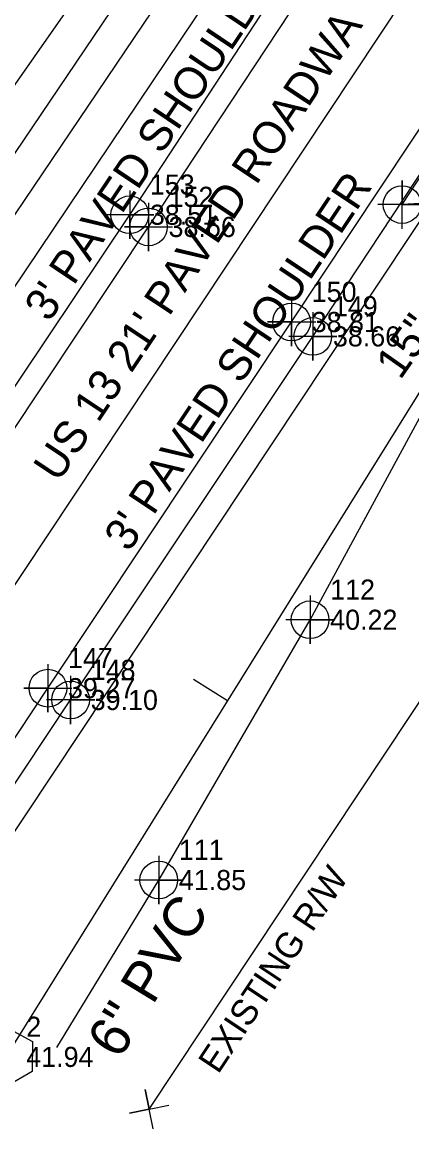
# Model space of a CAD drawing. Extents: x 2603627 to 2605187, y 896619 to 899063.
# Drawn here: x 2604072.2 to 2604120.7, y 897381.5 to 897519.1 of the extents above; entities that cross this region are included whole.
import ezdxf

# ---------------------------------------------------------------- set-up
doc = ezdxf.new("R2010")
doc.units = 0
for name, color, linetype in [('CTL GPS Vertical CELL', 7, 'Continuous'), ('CTL GPS Vertical Cogo Elevation', 7, 'Continuous'), ('CTL GPS Vertical Cogo Number', 7, 'Continuous'), ('Exist Horizontal Alignment', 7, 'Continuous'), ('Exist Horizontal Baseline Alignment', 7, 'Continuous'), ('Exist Horizontal Baseline Alignment Tick small', 7, 'Continuous'), ('Exist Property Corner CELL', 7, 'Continuous'), ('Exist Right of Way Line', 7, 'Continuous'), ('Exist Right of Way Line Text', 7, 'Continuous'), ('Exist Roads EOP', 7, 'Continuous'), ('Exist Roads EOP Cogo Elevation', 7, 'Continuous'), ('Exist Roads EOP Cogo Number', 7, 'Continuous'), ('Exist Roads EOP Cogo Point CELL', 7, 'Continuous'), ('Exist Roads EOP Text', 7, 'Continuous'), ('Exist Roads EOT', 7, 'Continuous'), ('Exist Roads EOT Cogo Elevation', 7, 'Continuous'), ('Exist Roads EOT Cogo Number', 7, 'Continuous'), ('Exist Roads EOT Cogo Point CELL', 7, 'Continuous'), ('Exist Roads EOT Text', 7, 'Continuous'), ('Exist Roads Soil', 7, 'Continuous'), ('Exist Roads Soil Cogo Point CELL', 7, 'Continuous'), ('Exist Structure Minor Pipes RCP 15 Inch Text', 7, 'Continuous'), ('Exist Utilities Telephone UG Cable SUE LOS C', 7, 'Continuous'), ('Exist Utilities Telephone UG FO SUE LOS C', 7, 'Continuous'), ('Exist Utilities Water UG Line SUE LOS B', 7, 'Continuous'), ('Exist Utilities Water UG Line SUE LOS B Cogo Elevation', 7, 'Continuous'), ('Exist Utilities Water UG Line SUE LOS B Cogo Number', 7, 'Continuous'), ('Exist Utilities Water UG Line SUE LOS B Cogo Point CELL', 7, 'Continuous'), ('Exist Utilities Water UG Line SUE LOS B Text', 7, 'Continuous'), ('Exist Vegetation Woods Line', 7, 'Continuous')]:
    doc.layers.add(name, color=color, linetype=linetype)

# ---------------------------------------------------------------- blocks, each defined once
blk = doc.blocks.new('EXIST UTILITIES WATER UG LINE SUE LOS B COGO POINT')
at = {"layer": 'Exist Utilities Water UG Line SUE LOS B Cogo Point CELL'}
blk.add_lwpolyline([(0, 0.06), (0, -0.06), (0, 0), (0.06, 0), (-0.06, 0)], dxfattribs=at)
blk.add_circle((0, 0), 0.0469, dxfattribs=at)
blk = doc.blocks.new('EXIST ROADS EOT COGO POINT')
at = {"layer": 'Exist Roads EOT Cogo Point CELL'}
blk.add_lwpolyline([(0, 0.06), (0, -0.06), (0, 0), (-0.06, 0), (0.06, 0)], dxfattribs=at)
blk.add_circle((0, 0), 0.0469, dxfattribs=at)
blk = doc.blocks.new('EXIST ROADS EOP COGO POINT')
at = {"layer": 'Exist Roads EOP Cogo Point CELL'}
blk.add_lwpolyline([(0, 0.06), (0, -0.06), (0, 0), (0.06, 0), (-0.06, 0)], dxfattribs=at)
blk.add_circle((0, 0), 0.0469, dxfattribs=at)
blk = doc.blocks.new('EXIST ROADS SOIL COGO POINT')
at = {"layer": 'Exist Roads Soil Cogo Point CELL'}
blk.add_lwpolyline([(0, -0.06), (0, 0.06), (0, 0), (0.06, 0), (-0.06, 0)], dxfattribs=at)
blk.add_circle((0, 0), 0.0469, dxfattribs=at)
blk = doc.blocks.new('CTL GPS VERTICAL')
at = {"layer": 'CTL GPS Vertical CELL'}
blk.add_line((0, 0), (0, 0), dxfattribs=at)
blk.add_lwpolyline([(-0.0646, 0.0374), (0.0004, 0.0737), (0.0654, 0.0379), (0.0644, -0.0366), (-0.0006, -0.0743), (-0.0646, -0.0381)], close=True, dxfattribs=at)

msp = doc.modelspace()

# ---------------------------------------------------------------- linework, layer by layer
at = {"layer": 'Exist Horizontal Alignment'}
msp.add_line((2604046.33, 897411.6), (2604501.12, 898096.36), dxfattribs=at)
at = {"layer": 'Exist Horizontal Baseline Alignment'}
msp.add_line((2604070.2, 897390.44), (2604301.74, 897762.53), dxfattribs=at)
at = {"layer": 'Exist Horizontal Baseline Alignment Tick small'}
msp.add_line((2604097.75, 897434.72), (2604093.51, 897437.36), dxfattribs=at)
at = {"layer": 'Exist Property Corner CELL'}
msp.add_line((2604087.98, 897383.94), (2604087.98, 897383.94), dxfattribs=at)
msp.add_lwpolyline([(2604088.48, 897381.49), (2604087.49, 897386.39), (2604087.98, 897383.94), (2604085.53, 897383.44), (2604090.43, 897384.43)], dxfattribs=at)
at = {"layer": 'Exist Right of Way Line'}
msp.add_line((2604087.98, 897383.94), (2604542.77, 898068.69), dxfattribs=at)
at = {"layer": 'Exist Roads EOP'}
for points in [[(2604034.94, 897419.16), (2604054.97, 897449.51), (2604085.58, 897495.18), (2604114.88, 897539.87), (2604143.93, 897583.57), (2604172.72, 897627.19), (2604201.64, 897670.62), (2604230.5, 897714.45), (2604261.1, 897760.21), (2604291.23, 897805.76), (2604320.82, 897850.24), (2604350.34, 897894.81), (2604379.01, 897938.02), (2604408.4, 897982.56), (2604438.29, 898027.28), (2604468.22, 898072.28), (2604496.92, 898115.7)], [(2604057.72, 897404.05), (2604078.22, 897434.83), (2604108.36, 897480.05), (2604137.93, 897524.86), (2604167.35, 897568.96), (2604196.06, 897612.17), (2604224.86, 897655.68), (2604253.51, 897698.95), (2604283.96, 897744.64), (2604314.74, 897791.03), (2604343.97, 897835.34), (2604373.31, 897879.6), (2604402.1, 897923.18), (2604431.64, 897967.59), (2604461.24, 898012.02), (2604491.05, 898056.88), (2604519.7, 898100.47)]]:
    msp.add_lwpolyline(points, dxfattribs=at)
at = {"layer": 'Exist Roads EOT'}
for points in [[(2604037.37, 897417.54), (2604057.46, 897447.93), (2604087.91, 897493.66), (2604117.35, 897538.28), (2604146.54, 897581.98), (2604175.28, 897625.51), (2604204.1, 897668.97), (2604233.05, 897712.63), (2604263.81, 897758.51), (2604293.89, 897804.07), (2604323.3, 897848.54), (2604352.86, 897893.08), (2604381.65, 897936.11), (2604411.04, 897980.65), (2604440.78, 898025.82), (2604470.61, 898070.74), (2604499.36, 898114.11)], [(2604055.13, 897405.77), (2604075.39, 897436.3), (2604105.72, 897481.84), (2604135.41, 897526.58), (2604164.51, 897570.47), (2604193.14, 897613.84), (2604222.02, 897657.58), (2604250.73, 897700.63), (2604281.08, 897746.07), (2604311.9, 897792.56), (2604341.37, 897836.94), (2604370.82, 897881.24), (2604399.64, 897924.71), (2604429.03, 897968.88), (2604458.85, 898013.95), (2604488.44, 898058.33), (2604517.14, 898101.52)]]:
    msp.add_lwpolyline(points, dxfattribs=at)
at = {"layer": 'Exist Roads Soil'}
msp.add_lwpolyline([(2604130.1, 897512.63), (2604131.01, 897508.25), (2604132.19, 897504.92), (2604126.99, 897496.75), (2604123.93, 897496.72), (2604119.47, 897496.44), (2604130.1, 897512.63)], dxfattribs=at)
at = {"layer": 'Exist Utilities Telephone UG Cable SUE LOS C'}
for p, q in [((2604060.46, 897402.24), (2604201.56, 897614.6)), ((2604028.87, 897423.18), (2604109.59, 897543.22))]:
    msp.add_line(p, q, dxfattribs=at)
at = {"layer": 'Exist Utilities Telephone UG FO SUE LOS C'}
for p, q in [((2604020.98, 897428.41), (2604461.82, 898080.46)), ((2604024.53, 897426.06), (2604465.37, 898078.1))]:
    msp.add_line(p, q, dxfattribs=at)
at = {"layer": 'Exist Utilities Water UG Line SUE LOS B'}
msp.add_lwpolyline([(2604076.5, 897391.6), (2604089.19, 897412.44), (2604108.02, 897444.81), (2604130.46, 897486.17), (2604138.61, 897502.5), (2604141.74, 897510.42), (2604157.29, 897542.11), (2604195.61, 897598.86), (2604232.99, 897655.2), (2604269.72, 897709.19), (2604303.43, 897758.71), (2604343.24, 897819.02), (2604371.6, 897861.28), (2604402.52, 897906.63), (2604434.42, 897955.25), (2604460.63, 897996.69), (2604477.79, 898022.59), (2604502.25, 898059.64), (2604529.4, 898098.89), (2604530.47, 898100.43), (2604537.02, 898109.88), (2604550.55, 898129.28)], dxfattribs=at)
at = {"layer": 'Exist Vegetation Woods Line'}
msp.add_lwpolyline([(2604185.5, 897674.67), (2604015.65, 897431.94)], dxfattribs=at)

# ---------------------------------------------------------------- block references
at = {"layer": 'CTL GPS Vertical CELL', "xscale": 50, "yscale": 50}
msp.add_blockref('CTL GPS VERTICAL', (2604070.2, 897390.44), dxfattribs=at)
at = {"layer": 'Exist Roads EOP Cogo Point CELL', "xscale": 50, "yscale": 50}
for p in [(2604085.58, 897495.18), (2604108.36, 897480.05), (2604078.22, 897434.83)]:
    msp.add_blockref('EXIST ROADS EOP COGO POINT', p, dxfattribs=at)
at = {"layer": 'Exist Roads EOT Cogo Point CELL', "xscale": 50, "yscale": 50}
for p in [(2604087.91, 897493.66), (2604105.72, 897481.84), (2604075.39, 897436.3)]:
    msp.add_blockref('EXIST ROADS EOT COGO POINT', p, dxfattribs=at)
at = {"layer": 'Exist Roads Soil Cogo Point CELL', "xscale": 50, "yscale": 50}
msp.add_blockref('EXIST ROADS SOIL COGO POINT', (2604119.47, 897496.44), dxfattribs=at)
at = {"layer": 'Exist Utilities Water UG Line SUE LOS B Cogo Point CELL', "xscale": 50, "yscale": 50}
for p in [(2604108.02, 897444.81), (2604089.19, 897412.44)]:
    msp.add_blockref('EXIST UTILITIES WATER UG LINE SUE LOS B COGO POINT', p, dxfattribs=at)

# ---------------------------------------------------------------- texts
at = {"layer": 'CTL GPS Vertical Cogo Elevation'}
msp.add_text('41.94', height=2.5, dxfattribs=at).set_placement((2604072.7, 897389.19))
at = {"layer": 'CTL GPS Vertical Cogo Number'}
msp.add_text('2', height=2.5, dxfattribs=at).set_placement((2604072.7, 897392.94))
at = {"layer": 'Exist Right of Way Line Text'}
msp.add_text('EXISTING R/W', height=3.2, rotation=56.4094, dxfattribs=at).set_placement((2604096.58, 897388.2))
at = {"layer": 'Exist Roads EOP Cogo Elevation'}
for s, p in [('38.51', (2604088.08, 897493.93)), ('38.66', (2604110.86, 897478.8)), ('39.10', (2604080.72, 897433.58))]:
    msp.add_text(s, height=2.5, dxfattribs=at).set_placement(p)
at = {"layer": 'Exist Roads EOP Cogo Number'}
for s, p in [('153', (2604088.08, 897497.68)), ('149', (2604110.86, 897482.55)), ('148', (2604080.72, 897437.33))]:
    msp.add_text(s, height=2.5, dxfattribs=at).set_placement(p)
at = {"layer": 'Exist Roads EOP Text'}
for rotation, p in [(56.1634, (2604075.55, 897481.7)), (56.322, (2604085.48, 897453.1))]:
    msp.add_text("3' PAVED SHOULDER", height=4, rotation=rotation, dxfattribs=at).set_placement(p)
at = {"layer": 'Exist Roads EOT Cogo Elevation'}
for s, p in [('38.66', (2604090.41, 897492.41)), ('38.81', (2604108.22, 897480.59)), ('39.27', (2604077.89, 897435.05))]:
    msp.add_text(s, height=2.5, dxfattribs=at).set_placement(p)
at = {"layer": 'Exist Roads EOT Cogo Number'}
for s, p in [('152', (2604090.41, 897496.16)), ('150', (2604108.22, 897484.34)), ('147', (2604077.89, 897438.8))]:
    msp.add_text(s, height=2.5, dxfattribs=at).set_placement(p)
at = {"layer": 'Exist Roads EOT Text'}
msp.add_text(" US 13 21' PAVED ROADWAY", height=4, rotation=56.3361, dxfattribs=at).set_placement((2604075.88, 897460.53))
at = {"layer": 'Exist Structure Minor Pipes RCP 15 Inch Text'}
msp.add_text('15" RCP', height=4, rotation=54.9355, dxfattribs=at).set_placement((2604119.23, 897474.53))
at = {"layer": 'Exist Utilities Water UG Line SUE LOS B Cogo Elevation'}
for s, p in [('40.22', (2604110.52, 897443.56)), ('41.85', (2604091.69, 897411.19))]:
    msp.add_text(s, height=2.5, dxfattribs=at).set_placement(p)
at = {"layer": 'Exist Utilities Water UG Line SUE LOS B Cogo Number'}
for s, p in [('112', (2604110.52, 897447.31)), ('111', (2604091.69, 897414.94))]:
    msp.add_text(s, height=2.5, dxfattribs=at).set_placement(p)
at = {"layer": 'Exist Utilities Water UG Line SUE LOS B Text'}
msp.add_text('6" PVC', height=5, rotation=58.6639, dxfattribs=at).set_placement((2604084.31, 897390))

doc.saveas('drawing.dxf')
